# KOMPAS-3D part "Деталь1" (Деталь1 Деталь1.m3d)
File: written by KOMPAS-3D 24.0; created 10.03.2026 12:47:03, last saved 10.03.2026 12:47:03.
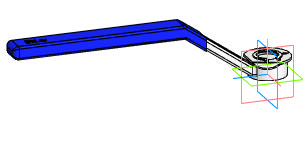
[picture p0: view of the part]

Document properties: Автор: R2D2; Полное имя файла: E:\Работа\Зайцев\BV3232P(4pc)-FP-3WL-F-ISO-H Кран шаровой DN.ru Ду15-100 Ру16\DN50\исходные материалы\Деталь1 Деталь1.m3d

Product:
- Body: Твердое тело1  | qty 1
- Part/product: Деталь1
    additional columns: Типовые

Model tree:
1. Твердое тело1  (labels: Твердое тело1)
